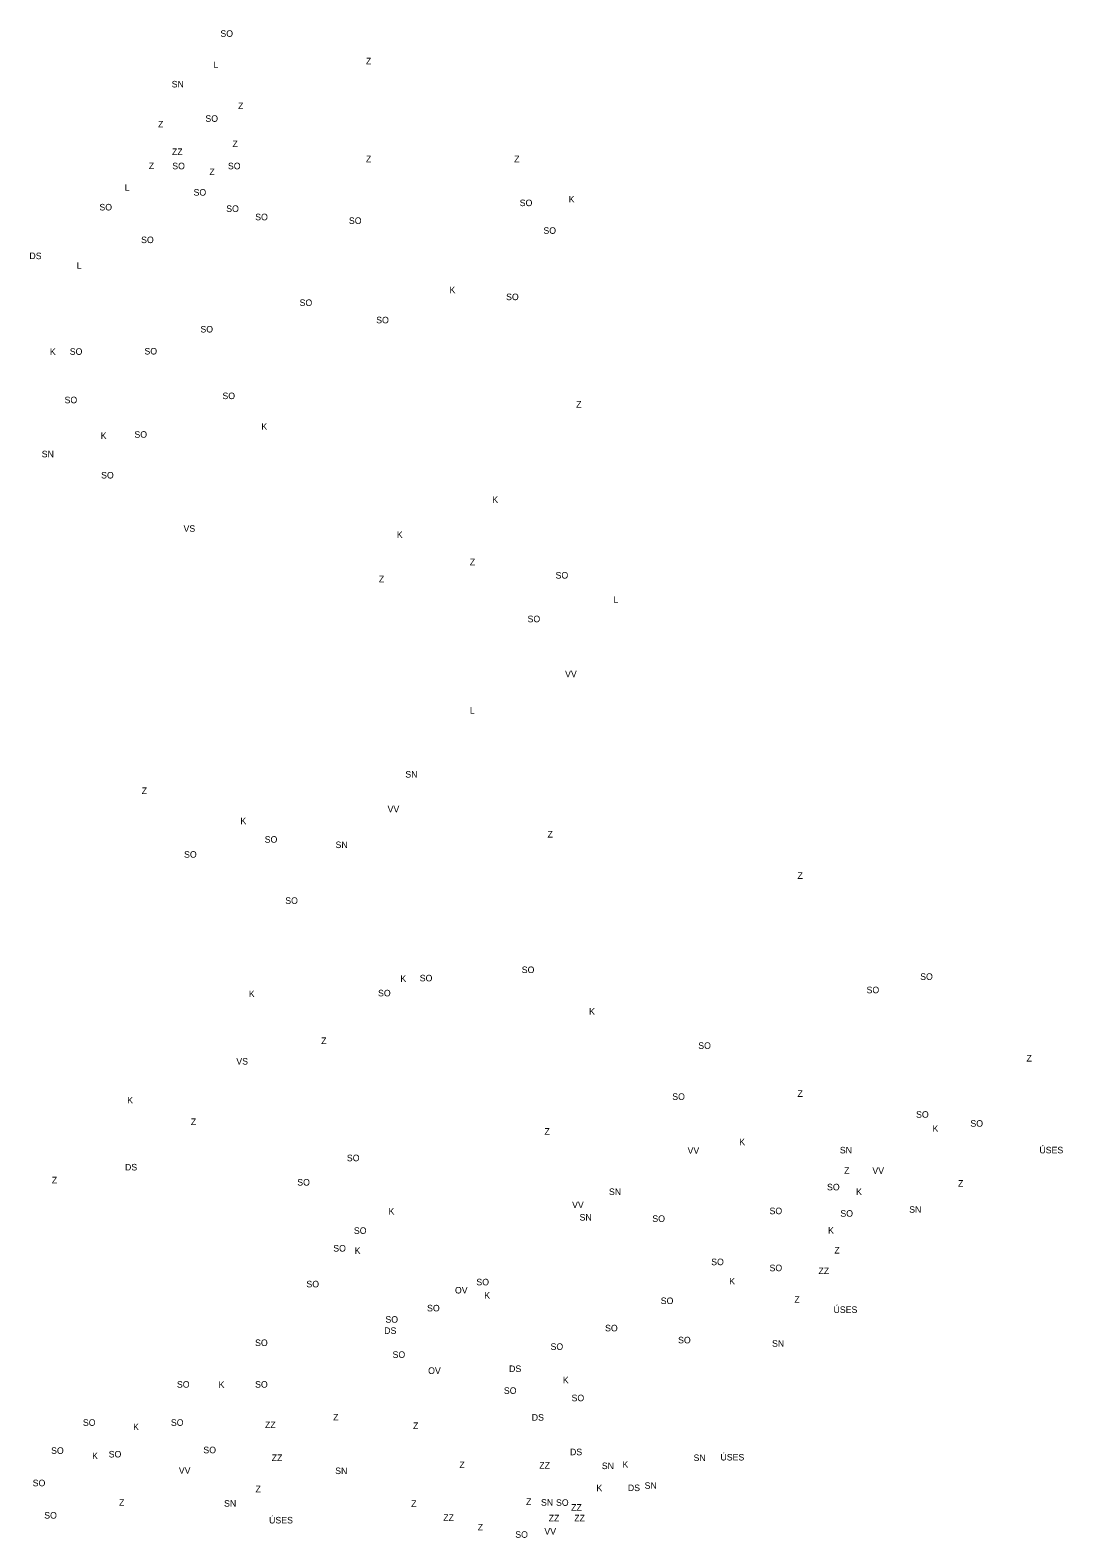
# Model space of a CAD drawing. Extents: x -445021 to -431236, y -1134464 to -1129615.
# Drawn here: x -442128 to -440551, y -1132144 to -1129841 of the extents above; entities that cross this region are included whole.
import ezdxf

# ---------------------------------------------------------------- set-up
doc = ezdxf.new("R2010")
doc.units = 0
doc.layers.add('Vrstva 84', color=7, linetype='Continuous')

msp = doc.modelspace()

# ---------------------------------------------------------------- texts
at = {"layer": 'Vrstva 84'}
for s, p in [('SO', (-441837.9, -1129850.8)), ('L', (-441848.5, -1129898.6)), ('Z', (-441615.6, -1129892.8)), ('SN', (-441912.3, -1129928.1)), ('Z', (-441810.9, -1129961.2)), ('Z', (-441933.1, -1129989.2)), ('SO', (-441860.8, -1129980.6)), ('ZZ', (-441911.9, -1130031.3)), ('Z', (-441819.5, -1130019.3)), ('Z', (-441947.3, -1130052.9)), ('SO', (-441911.4, -1130053.1)), ('Z', (-441854.7, -1130062)), ('SO', (-441826.4, -1130053.1)), ('Z', (-441615.6, -1130042.4)), ('Z', (-441389.1, -1130042.4)), ('L', (-441984, -1130086)), ('SO', (-441878.9, -1130093.4)), ('SO', (-441380.7, -1130109.4)), ('K', (-441305.9, -1130103.8)), ('SO', (-442022.7, -1130116)), ('SO', (-441829, -1130118.3)), ('SO', (-441784.7, -1130131)), ('SO', (-441641.6, -1130136.6)), ('SO', (-441344.5, -1130151.7)), ('SO', (-441959, -1130165.9)), ('DS', (-442129.6, -1130190.4)), ('L', (-442057.3, -1130205.1)), ('K', (-441488, -1130242.4)), ('SO', (-441716.9, -1130261.9)), ('SO', (-441401.5, -1130253)), ('SO', (-441599.9, -1130288.4)), ('SO', (-441868.4, -1130302.4)), ('K', (-442098.3, -1130336.8)), ('SO', (-442068, -1130336.5)), ('SO', (-441953.9, -1130336)), ('SO', (-441834.8, -1130404.2)), ('SO', (-442075.9, -1130410.5)), ('Z', (-441294.4, -1130417.1)), ('K', (-441775.3, -1130451.1)), ('K', (-442020.7, -1130465.1)), ('SO', (-441969.2, -1130463.2)), ('SN', (-442110.8, -1130493.1)), ('SO', (-442020.1, -1130525.4)), ('K', (-441422.6, -1130562.7)), ('VS', (-441894.2, -1130606.9)), ('K', (-441568.4, -1130616.3)), ('Z', (-441456.9, -1130658)), ('Z', (-441595.8, -1130683.9)), ('SO', (-441325.9, -1130678.3)), ('L', (-441237.4, -1130715.5)), ('SO', (-441368.7, -1130745)), ('VV', (-441311.4, -1130829)), ('L', (-441456.9, -1130884.5)), ('SN', (-441555.4, -1130982.3)), ('Z', (-441958.1, -1131007.4)), ('K', (-441807.3, -1131053.5)), ('VV', (-441582.5, -1131035.4)), ('Z', (-441338.2, -1131073.9)), ('SO', (-441770.2, -1131081.8)), ('SN', (-441662, -1131090)), ('SO', (-441893.4, -1131104.7)), ('Z', (-440956.4, -1131137)), ('SO', (-441738.8, -1131175.2)), ('SO', (-441377.6, -1131280.9)), ('K', (-441563, -1131294.4)), ('SO', (-441533.4, -1131293.6)), ('SO', (-440769, -1131291.3)), ('K', (-441794.4, -1131317.6)), ('SO', (-441597.1, -1131316.5)), ('SO', (-440850.9, -1131311.7)), ('K', (-441274.7, -1131344.5)), ('Z', (-441683.9, -1131389.3)), ('SO', (-441108, -1131396.7)), ('VS', (-441813.6, -1131420.7)), ('Z', (-440606.6, -1131416)), ('K', (-441980.1, -1131480.1)), ('SO', (-441147.7, -1131474.6)), ('Z', (-440956.4, -1131470)), ('Z', (-441883, -1131513)), ('SO', (-440775.3, -1131501.9)), ('SO', (-440692.3, -1131515.6)), ('Z', (-441342.8, -1131527.8)), ('K', (-440750.1, -1131523.4)), ('VV', (-441124.3, -1131556.9)), ('K', (-441045.4, -1131543.8)), ('SN', (-440891.7, -1131556.4)), ('ÚSES', (-440586.9, -1131556.3)), ('DS', (-441983.6, -1131582.4)), ('SO', (-441644.7, -1131568.3)), ('Z', (-442095.3, -1131602.1)), ('SO', (-441720.5, -1131605.5)), ('Z', (-440885.1, -1131587.4)), ('VV', (-440842, -1131587.7)), ('Z', (-440711.2, -1131607.2)), ('SN', (-441244.4, -1131619.9)), ('SO', (-440911.3, -1131612.8)), ('K', (-440866.9, -1131619.9)), ('K', (-441581.1, -1131649.8)), ('VV', (-441300.7, -1131639.9)), ('SO', (-440999.1, -1131649.2)), ('SO', (-440890.9, -1131653.1)), ('SN', (-440785.8, -1131647)), ('SN', (-441289.3, -1131659)), ('SO', (-441178.1, -1131661)), ('SO', (-441634, -1131679.3)), ('K', (-440909.7, -1131678.9)), ('SO', (-441665.5, -1131706.3)), ('K', (-441632.8, -1131709.9)), ('Z', (-440900.1, -1131709.3)), ('SO', (-441088.2, -1131727.1)), ('SO', (-440999.1, -1131736.3)), ('ZZ', (-440924.4, -1131740.8)), ('SO', (-441706.5, -1131761)), ('SO', (-441446.9, -1131757.9)), ('K', (-441060.6, -1131756.6)), ('OV', (-441479.6, -1131770.3)), ('K', (-441434.8, -1131778.2)), ('SO', (-441165.3, -1131786.5)), ('Z', (-440961.2, -1131784.6)), ('SO', (-441585.8, -1131815)), ('SO', (-441522.2, -1131797.7)), ('ÚSES', (-440901.4, -1131800)), ('DS', (-441587.7, -1131832.1)), ('SO', (-441250.3, -1131828.2)), ('SO', (-441784.9, -1131850.6)), ('SO', (-441333.6, -1131856.5)), ('SO', (-441138.8, -1131846.5)), ('SN', (-440995.3, -1131851.7)), ('SO', (-441574.9, -1131868.7)), ('OV', (-441520.6, -1131893.2)), ('DS', (-441396.9, -1131890.3)), ('SO', (-441904.3, -1131914.2)), ('K', (-441840.6, -1131914.6)), ('SO', (-441784.9, -1131914.2)), ('SO', (-441404.9, -1131923.7)), ('K', (-441314.9, -1131907.5)), ('SO', (-441301.5, -1131934.9)), ('SO', (-442047.9, -1131972.5)), ('SO', (-441913.5, -1131972.5)), ('ZZ', (-441769.8, -1131975.9)), ('Z', (-441665.6, -1131964.2)), ('DS', (-441362.3, -1131964.6)), ('K', (-441971.2, -1131979.1)), ('Z', (-441543.7, -1131977.4)), ('SO', (-442096.5, -1132015.3)), ('SO', (-442008.5, -1132020.8)), ('SO', (-441863.9, -1132014.4)), ('DS', (-441303.9, -1132017.4)), ('K', (-442033.8, -1132023.4)), ('ZZ', (-441759.5, -1132026.2)), ('Z', (-441472.9, -1132037.1)), ('ZZ', (-441350.8, -1132037.9)), ('SN', (-441255.3, -1132038.6)), ('K', (-441223.7, -1132036.5)), ('SN', (-441115.2, -1132026.3)), ('ÚSES', (-441074.1, -1132025.4)), ('SO', (-442124.6, -1132064.8)), ('VV', (-441901.4, -1132045.7)), ('SN', (-441662.5, -1132046.2)), ('Z', (-441784.2, -1132074)), ('K', (-441263.5, -1132072.5)), ('DS', (-441215.5, -1132072.2)), ('SN', (-441189.9, -1132068.7)), ('SO', (-442107, -1132114.2)), ('Z', (-441992.7, -1132094.6)), ('SN', (-441832.3, -1132096)), ('Z', (-441546.5, -1132096.4)), ('Z', (-441371, -1132093.3)), ('SN', (-441348.2, -1132094.5)), ('SO', (-441325.3, -1132094.7)), ('ZZ', (-441302.1, -1132102.1)), ('ÚSES', (-441763.5, -1132121.6)), ('ZZ', (-441497.5, -1132117.7)), ('Z', (-441444.8, -1132132.3)), ('ZZ', (-441336.4, -1132118.4)), ('ZZ', (-441297.4, -1132118.4)), ('SO', (-441387.5, -1132143.5)), ('VV', (-441343, -1132138.7))]:
    msp.add_text(s, height=10, dxfattribs=at).set_placement(p)

doc.saveas('drawing.dxf')
